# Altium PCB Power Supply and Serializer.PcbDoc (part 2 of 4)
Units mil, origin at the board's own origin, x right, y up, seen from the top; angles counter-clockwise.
Board outline 986 x 985 mil, 8 copper layers (TOP, GND1, INNER1, GND2, PWR1, INNER2, GND3, BOTTOM), stack 60.4 mil thick; 91 components, 64 nets, 288 pads, 200 vias.
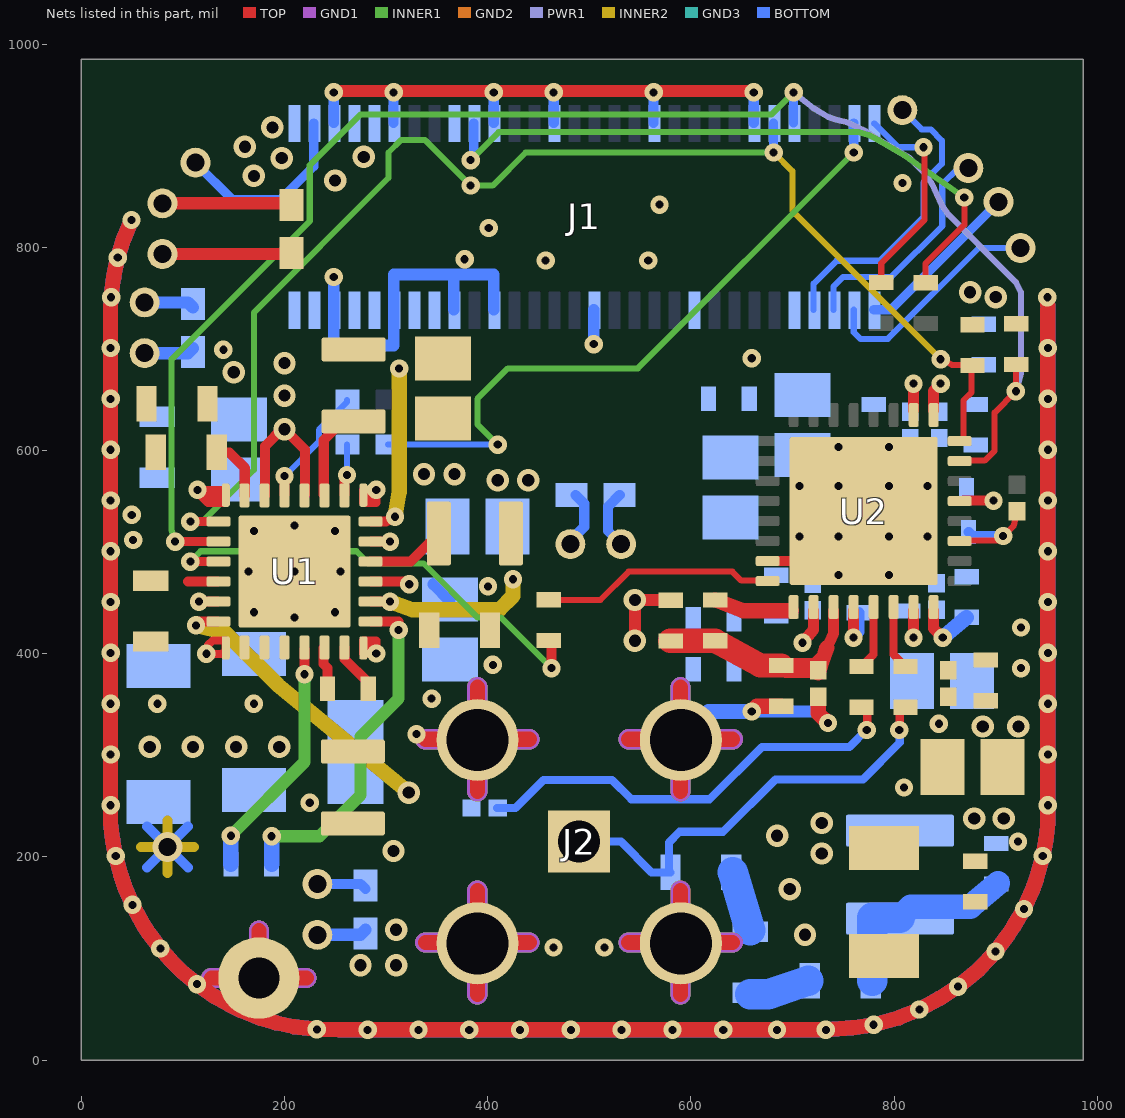
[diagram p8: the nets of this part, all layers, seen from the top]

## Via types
v1: diameter 18, hole 8, TOP to BOTTOM, 147 vias
v2: diameter 22, hole 12, TOP to BOTTOM, 36 vias
v3: diameter 19.68, hole 7.87, TOP to BOTTOM, 17 vias

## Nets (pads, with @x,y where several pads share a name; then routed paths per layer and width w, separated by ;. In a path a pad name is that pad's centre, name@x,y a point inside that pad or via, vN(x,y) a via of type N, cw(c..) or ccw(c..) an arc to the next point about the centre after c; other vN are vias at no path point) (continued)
DGND: C2.2 C3.2 C4.2 C5.2 C6.2 C7.2 C8.2 C9.2 C10.2 C11.2 C12.2 C13.2 C15.2 C16.2 C18.1 C19.2 C20.2 C21.2 C22.2 C24.2 C25.2 C26.2 C27.2 C28.2 C29.2 C30.2 C31.2 C32.2 C33.2 C34.2 C35.2 J1.5 J1.6 J1.11 J1.12 J1.18 J1.21 J1.22 J1.27 J1.32 J1.37 J1.42 J1.47 J1.52 J2.2 J2.3 J2.4 J2.5 R10.1 R14.1 R15.1 TP15.1 U1.5 U1.25 U1.A1 U1.A2 U1.A3 U1.A4 U2.7 U2.33@770,540.39 | length 11901.1
  TOP w8: v1@119.3,561.3 125.8,554.8 U1.A1@138.38,554.8 ; v1@119.3,561.3 138.38,561.3 U1.A1@138.38,554.8 ; v1@119.3,561.3 v1(114.3,561.3) 114.3,558.8 124.58,548.52 142.08,548.52 138.38,552.22 U1.A1@138.38,554.8 ; U1.A3@277.52,413.08 290.3,413.08 v1(290.3,400.3) ; U1.A3@277.52,413.08 277.52,400.3 v1(290.3,400.3) ; U1.A3@277.52,413.08 v1(290.3,400.3) ; U1.A4@277.52,548.52 277.52,561.3 v1(290.3,561.3) ; U1.A4@277.52,548.52 v1(290.3,561.3) ; U1.A4@277.52,548.52 290.3,548.52 v1(290.3,561.3) ; v1@124.8,399.8 138.52,399.8 142.08,403.36 142.08,413.08 129.3,413.08 124.8,408.58 v1@124.8,399.8
  TOP w9.8: v1(115.8,451.27) U1.5@133.89,451.27 ; U2.7@675.51,491.18 720.79,491.18 U2.33@770,540.39
  TOP w12: v1(248.4,952.5) 249.7,953.8 306.1,953.8 v1(307.4,952.5) 308.7,953.8 404.6,953.8 v1(405.9,952.5) 407.2,953.8 463.6,953.8 v1(464.9,952.5) 466.2,953.8 562,953.8 v1(563.3,952.5) 564.6,953.8 660.5,953.8 v1(661.8,952.5)
  TOP w15: v1(49.3,826.8) 41.3,807.3 v1(35.8,789.8) 31.8,770.3 v1(29.3,750.8) 28.8,738.3 v1(28.8,700.8) v1(28.8,650.8) v1(28.8,600.8) v1(28.8,550.8) v1(28.8,500.8) v1(28.8,450.8) v1(28.8,400.8) v1(28.8,350.8) v1(28.8,300.8) v1(28.8,250.8) 28.8,233.3 30.8,216.8 v1(33.8,200.8) 38.8,182.3 43.8,167.8 v1(50.3,152.8) 59.8,135.3 66.8,124.3 v1(77.8,109.8) 88.3,97.8 98.8,87.3 v1(113.8,74.8) 130.8,62.8 145.3,54.8 158.3,48.3 176.3,41.3 191.3,36.8 209.3,32.8 v1(231.8,30.3) 253.8,29.8 v1(281.8,29.8) v1(331.8,29.8) v1(381.8,29.8) v1(431.8,29.8) v1(481.8,29.8) v1(531.8,29.8) v1(581.8,29.8) v1(631.8,29.8) v1(684.8,29.8) v1(732.8,29.8) 758.8,31.8 v1(779.8,34.8) 804.8,41.8 v1(824.8,49.8) 844.8,60.8 v1(862.8,72.3) 883.8,89.8 v1(899.8,106.8) 911.8,122.8 917.8,131.8 v1(927.8,148.8) 935.8,166.8 939.8,177.8 v1(946.3,200.8) 949.3,216.8 951.3,233.3 v1(951.3,250.8) v1(951.3,300.8) v1(951.3,350.8) v1(951.3,400.8) v1(951.3,450.8) v1(951.3,500.8) v1(951.3,550.8) v1(951.3,600.8) v1(951.3,650.8) v1(951.3,700.8) 951.3,738.3 v1(950.8,750.8) ; 127.98,80.8 TP15.1@174.8,80.8 ; 174.8,127.62 TP15.1@174.8,80.8 ; 221.62,80.8 TP15.1@174.8,80.8 ; 338.61,115.8 J2.5@389.8,115.8 ; 338.61,315.8 J2.2@389.8,315.8 ; 389.8,64.61 J2.5@389.8,115.8 ; 389.8,166.99 J2.5@389.8,115.8 ; 389.8,264.61 J2.2@389.8,315.8 ; 389.8,366.99 J2.2@389.8,315.8 ; 440.99,115.8 J2.5@389.8,115.8 ; 440.99,315.8 J2.2@389.8,315.8 ; 538.61,115.8 J2.4@589.8,115.8 ; 538.61,315.8 J2.3@589.8,315.8 ; 589.8,64.61 J2.4@589.8,115.8 ; 589.8,166.99 J2.4@589.8,115.8 ; 589.8,264.61 J2.3@589.8,315.8 ; 589.8,366.99 J2.3@589.8,315.8 ; 640.99,115.8 J2.4@589.8,115.8 ; 640.99,315.8 J2.3@589.8,315.8 ; v1(659.8,343.22) 664.8,348.22 C21.2@688.8,348.22 ; C22.2@725.3,355.31 725.3,341.3 v1(734.8,331.8)
  GND1 w20: 127.98,80.8 TP15.1@174.8,80.8 ; 174.8,127.62 TP15.1@174.8,80.8 ; 221.62,80.8 TP15.1@174.8,80.8 ; 338.61,115.8 J2.5@389.8,115.8 ; 338.61,315.8 J2.2@389.8,315.8 ; 389.8,64.61 J2.5@389.8,115.8 ; 389.8,166.99 J2.5@389.8,115.8 ; 389.8,264.61 J2.2@389.8,315.8 ; 389.8,366.99 J2.2@389.8,315.8 ; 440.99,115.8 J2.5@389.8,115.8 ; 440.99,315.8 J2.2@389.8,315.8 ; 538.61,115.8 J2.4@589.8,115.8 ; 538.61,315.8 J2.3@589.8,315.8 ; 589.8,64.61 J2.4@589.8,115.8 ; 589.8,166.99 J2.4@589.8,115.8 ; 589.8,264.61 J2.3@589.8,315.8 ; 589.8,366.99 J2.3@589.8,315.8 ; 640.99,115.8 J2.4@589.8,115.8 ; 640.99,315.8 J2.3@589.8,315.8
  INNER1 w20: 127.98,80.8 TP15.1@174.8,80.8 ; 174.8,127.62 TP15.1@174.8,80.8 ; 221.62,80.8 TP15.1@174.8,80.8 ; 338.61,115.8 J2.5@389.8,115.8 ; 338.61,315.8 J2.2@389.8,315.8 ; 389.8,64.61 J2.5@389.8,115.8 ; 389.8,166.99 J2.5@389.8,115.8 ; 389.8,264.61 J2.2@389.8,315.8 ; 389.8,366.99 J2.2@389.8,315.8 ; 440.99,115.8 J2.5@389.8,115.8 ; 440.99,315.8 J2.2@389.8,315.8 ; 538.61,115.8 J2.4@589.8,115.8 ; 538.61,315.8 J2.3@589.8,315.8 ; 589.8,64.61 J2.4@589.8,115.8 ; 589.8,166.99 J2.4@589.8,115.8 ; 589.8,264.61 J2.3@589.8,315.8 ; 589.8,366.99 J2.3@589.8,315.8 ; 640.99,115.8 J2.4@589.8,115.8 ; 640.99,315.8 J2.3@589.8,315.8
  GND2 w20: 127.98,80.8 TP15.1@174.8,80.8 ; 174.8,127.62 TP15.1@174.8,80.8 ; 221.62,80.8 TP15.1@174.8,80.8 ; 338.61,115.8 J2.5@389.8,115.8 ; 338.61,315.8 J2.2@389.8,315.8 ; 389.8,64.61 J2.5@389.8,115.8 ; 389.8,166.99 J2.5@389.8,115.8 ; 389.8,264.61 J2.2@389.8,315.8 ; 389.8,366.99 J2.2@389.8,315.8 ; 440.99,115.8 J2.5@389.8,115.8 ; 440.99,315.8 J2.2@389.8,315.8 ; 538.61,115.8 J2.4@589.8,115.8 ; 538.61,315.8 J2.3@589.8,315.8 ; 589.8,64.61 J2.4@589.8,115.8 ; 589.8,166.99 J2.4@589.8,115.8 ; 589.8,264.61 J2.3@589.8,315.8 ; 589.8,366.99 J2.3@589.8,315.8 ; 640.99,115.8 J2.4@589.8,115.8 ; 640.99,315.8 J2.3@589.8,315.8
  GND3 w20: 127.98,80.8 TP15.1@174.8,80.8 ; 174.8,127.62 TP15.1@174.8,80.8 ; 221.62,80.8 TP15.1@174.8,80.8 ; 338.61,115.8 J2.5@389.8,115.8 ; 338.61,315.8 J2.2@389.8,315.8 ; 389.8,64.61 J2.5@389.8,115.8 ; 389.8,166.99 J2.5@389.8,115.8 ; 389.8,264.61 J2.2@389.8,315.8 ; 389.8,366.99 J2.2@389.8,315.8 ; 440.99,115.8 J2.5@389.8,115.8 ; 440.99,315.8 J2.2@389.8,315.8 ; 538.61,115.8 J2.4@589.8,115.8 ; 538.61,315.8 J2.3@589.8,315.8 ; 589.8,64.61 J2.4@589.8,115.8 ; 589.8,264.61 J2.3@589.8,315.8 ; 589.8,366.99 J2.3@589.8,315.8 ; 640.99,115.8 J2.4@589.8,115.8 ; 640.99,315.8 J2.3@589.8,315.8
  BOTTOM w10: J1.5@248.4,922.4 v1(248.4,952.5) ; J1.11@307.4,922.4 v1(307.4,952.5) ; J1.21@405.9,922.4 v1(405.9,952.5) ; J1.27@464.9,922.4 v1(464.9,952.5) ; J1.37@563.3,922.4 v1(563.3,952.5) ; J1.47@661.8,922.4 v1(661.8,952.5)
  BOTTOM w11.5: v1(248.4,770.8) 248.4,703.3 307.4,703.3 307.4,773.3 366.5,773.3 ; J1.18@366.5,738.5 366.5,773.3 ; J1.22@405.9,738.5 405.9,773.3 366.5,773.3 ; v1(504.3,704.7) J1.32@504.3,738.5
  BOTTOM w12: v1(248.4,952.5) 249.7,953.8 306.1,953.8 v1(307.4,952.5) 308.7,953.8 404.6,953.8 v1(405.9,952.5) 407.2,953.8 463.6,953.8 v1(464.9,952.5) 466.2,953.8 562,953.8 v1(563.3,952.5) 564.6,953.8 660.5,953.8 v1(661.8,952.5) ; v1(659.8,343.22) 723.38,343.22 v1(734.8,331.8)
  BOTTOM w15: v1(49.3,826.8) 41.3,807.3 v1(35.8,789.8) 31.8,770.3 v1(29.3,750.8) 28.8,738.3 v1(28.8,700.8) v1(28.8,650.8) v1(28.8,600.8) v1(28.8,550.8) v1(28.8,500.8) v1(28.8,450.8) v1(28.8,400.8) v1(28.8,350.8) v1(28.8,300.8) v1(28.8,250.8) 28.8,233.3 30.8,216.8 v1(33.8,200.8) 38.8,182.3 43.8,167.8 v1(50.3,152.8) 59.8,135.3 66.8,124.3 v1(77.8,109.8) 88.3,97.8 98.8,87.3 v1(113.8,74.8) 130.8,62.8 145.3,54.8 158.3,48.3 176.3,41.3 191.3,36.8 209.3,32.8 v1(231.8,30.3) 253.8,29.8 v1(281.8,29.8) v1(331.8,29.8) v1(381.8,29.8) v1(431.8,29.8) v1(481.8,29.8) v1(531.8,29.8) v1(581.8,29.8) v1(631.8,29.8) v1(684.8,29.8) v1(732.8,29.8) 758.8,31.8 v1(779.8,34.8) 804.8,41.8 v1(824.8,49.8) 844.8,60.8 v1(862.8,72.3) 883.8,89.8 v1(899.8,106.8) 911.8,122.8 917.8,131.8 v1(927.8,148.8) 935.8,166.8 939.8,177.8 v1(946.3,200.8) 949.3,216.8 951.3,233.3 v1(951.3,250.8) v1(951.3,300.8) v1(951.3,350.8) v1(951.3,400.8) v1(951.3,450.8) v1(951.3,500.8) v1(951.3,550.8) v1(951.3,600.8) v1(951.3,650.8) v1(951.3,700.8) 951.3,738.3 v1(950.8,750.8) ; 126.98,80.8 TP15.1@174.8,80.8 222.62,80.8 ; 337.61,315.8 J2.2@389.8,315.8 ; 389.8,63.61 J2.5@389.8,115.8 ; 389.8,167.99 J2.5@389.8,115.8 ; 389.8,367.99 J2.2@389.8,315.8 ; 441.99,115.8 J2.5@389.8,115.8 ; 441.99,315.8 J2.2@389.8,315.8 ; 537.61,115.8 589.8,115.8 589.8,63.61 ; 537.61,315.8 589.8,315.8 617.22,343.22 v1(659.8,343.22)
  BOTTOM w20: TP15.1@174.8,80.8 TP15.1@187.3,93.3
  other v1: 464.8,110.8 514.8,110.8 809.8,268.3 329.8,320.8 844,331 74.8,350.8 169.8,350.8 344.8,355.8 924.8,385.8 405,389 123,400 924.8,425.8 169.8,440.8 249.8,440.8 51,512 169.8,520.8 249.8,520.8 49.64,536.67 659.8,690.8 457,787 558,787 377.3,788.3 401,819 569,842 808.3,863.3
  other v2: 712.3,123.3 697.3,168.3 684.8,220.8 337.3,576.8 367.3,576.8
  other v3: 209.86,435.59 745.2,477.4 794.8,477.4 164.58,480.86 209.86,480.86 255.13,480.86 707.01,515.59 745.2,515.59 794.8,515.59 832.99,515.59 209.86,526.14 707.01,565.2 745.2,565.2 794.8,565.2 832.99,565.2 745.2,603.39 794.8,603.39
DOUTN: C17.1 U2.13 | length 59.9
  TOP w8: C17.1@767.83,387.4 779.64,399.21 U2.13@779.64,442.37
DOUTN_C: C17.2 R10.2 | length 435.8
  TOP w8: C17.2@767.83,347.24 773.48,341.59 v1@773.48,325.8
  BOTTOM w8: R10.2@409.29,248.3 427.3,248.3 454.8,275.8 522.3,275.8 541.3,256.8 618.31,256.8 669.81,308.3 755.98,308.3 v1@773.48,325.8
  other v1: 773,325
DOUTP: C14.1 U2.14 | length 59.9
  TOP w8: U2.14@799.33,442.37 799.33,399.21 C14.1@811.14,387.4
DOUTP_C: C14.2 J2.1 L6.1 | length 436.7
  TOP w8: v1@805.48,325.8 805.48,341.58 C14.2@811.14,347.24
  BOTTOM w8: J2.1@490,215 531,215 561.2,184.8 L6.1@578.3,184.8 ; L6.1@579.8,184.8 L6.1@578.3,184.8 ; v1@805.48,325.8 805.48,312.54 769.24,276.3 683.07,276.3 631.57,224.8 588.8,224.8 578.3,214.3 L6.1@578.3,184.8
  other v1: 805,325
I2C_SCL: J1.49 R11.1 U1.1 U2.24 | length 1304.3
  TOP w6: v1(845.8,689.8) 856.8,684.22 876.3,684.22 876.3,657.29 868.23,649.22 U2.24@868.23,609.7
  TOP w9: v1(107.3,530.01) U1.1@133.89,530.01
  INNER1 w6: v1(107.3,530.01) 119.01,530.01 169.8,580.8 169.8,735.8 302.3,868.3 302.3,893.3 314.8,905.8 338.2,905.8 v1(383.2,860.8) 404.8,860.8 437.3,893.3 v1(681.4,893.3)
  INNER2 w6: v1(681.4,893.3) 699.8,874.9 699.8,835.8 v1(845.8,689.8)
  BOTTOM w9: v1(681.4,893.3) J1.49@681.4,922.4
I2C_SDA: J1.51 R12.1 U1.2 U2.23 | length 1536.4
  TOP w6: U2.23@868.23,590.01 889.01,590.01 898.8,599.8 898.8,637.3 v1(919.8,658.3) R12.1@919.8,684.22
  TOP w9: v1(92.3,510.33) U1.2@133.89,510.33
  INNER1 w6: v1(92.3,510.33) 88.8,521.8 88.8,689.8 224.8,825.8 224.8,880.8 274.8,930.8 679.4,930.8 v1(701.1,952.5)
  PWR1 w6: v1(701.1,952.5) 719.95,937.3 735.18,928.28 742.3,925.8 754.66,922.71 771.54,914.64 784.8,905.8 814.8,888.3 829.8,873.3 836.87,863.01 846.93,841.33 853.55,832.05 919.8,765.8 924.8,755.8 924.8,675.8 v1(919.8,658.3)
  BOTTOM w9: J1.51@701.1,922.4 v1(701.1,952.5)
IMG_GP2: J1.57 R6.1 | length 661.4
  INNER1 w6: v1(409.8,605.8) 389.8,625.8 389.8,650.8 419.8,680.8 547.7,680.8 v1(760.2,893.3)
  BOTTOM w6: R6.1@301.68,605.8 v1(409.8,605.8)
  BOTTOM w9: v1(760.2,893.3) J1.57@760.2,922.4
IMG_GP3: J1.59 R8.2 | length 209.3
  TOP w6: R8.2@787.3,765.38 787.3,784.3 829.8,826.8 829.8,897.61 v1(828.98,898.44)
  BOTTOM w6: J1.59@780.43,921.93 803.93,898.44 v1(828.98,898.44)
IMG_GP4: J1.54 TP4.1 | length 295.1
  BOTTOM w6: J1.54@720.8,738.5 720.8,764.3 743.3,786.8 785.8,786.8 828.8,829.8 828.8,863.81 847.04,882.05 847.04,904.96 836,916 827,916 TP4.1@808,935
IMG_GP5: J1.56 TP6.1 | length 228.1
  BOTTOM w6: J1.56@740.5,738.5 740.5,761.5 749.8,770.8 797.3,770.8 847.3,820.8 847.3,862.3 863,878 TP6.1@873,878
IMG_GP6: J1.58 TP7.1 | length 226
  BOTTOM w6: J1.58@760.2,738.5 760.2,716.4 766.8,709.8 793.8,709.8 883.3,799.3 TP7.1@924.3,799.3
IMG_HSYNC: J1.17
IMG_VSYNC: J1.19 R17.2 | length 653.4
  TOP w6: R17.2@830.8,765.38 830.8,783.8 869.05,822.05 v1(869.05,849.05)
  INNER1 w6: v1(383.2,885.8) 410.7,913.3 764.8,913.3 774.73,910.69 784.59,905.47 809.55,890.83 v1(869.05,849.05)
  BOTTOM w9: v1(383.2,885.8) 386.2,888.8 J1.19@386.2,922.4
LPF1: C23.2 U2.9 | length 79
  TOP w8: U2.9@698.8,442.37 U2.9@700.9,442.37
  TOP w15: C23.2@623.8,452.87 651.5,442.37 U2.9@698.8,442.37
LPF2: C35.1 U2.12 | length 53.3
  TOP w11: v1(759.96,415.8) U2.12@759.96,442.37
  BOTTOM w11: v1(759.96,415.8) 759.96,416.32 765.22,421.58 C35.1@765.22,440.38
NetC1_1: C1.1 L1.1 U1.11 | length 39.4
  TOP w10: U1.11@238.35,405.43 238.35,389.89 242.23,386.01 C1.1@242.23,367.66
NetC1_2: C1.2 U1.12 | length 50.1
  TOP w9.8: U1.12@259.07,406.06 259.07,394.74 282.3,371.51 C1.2@282.3,365.59
NetC4_1: C4.1 L1.2 R1.1 TP1.1 U1.6 | length 341.8
  TOP w9.8: v1(112.8,427.9) 116.49,431.59 U1.6@133.89,431.59
  INNER2 w15: v1(112.8,427.9) 141.66,420.94 193.6,369 v2(322.3,263.3)
  BOTTOM w10: TP1.1@232.3,173.3 274.88,173.3 R1.1@279.8,168.38
  other v1: 224.8,253.3
  other v2: 307.3,205.8
NetC5_1: C5.1 L2.2 R2.1 TP3.1 U1.18 | length 297.7
  TOP w9.8: U1.18@285.71,530.01 300.01,530.01 v1(308.8,534.8)
  TOP w12: TP3.1@79.8,793.3 199.88,793.3 R2.1@204.8,798.22
  INNER2 w15: v1(308.8,534.8) 312.8,558.92 v1(312.8,680.8)
NetC9_1: C9.1 L3.2 R3.1 TP9.1 U1.14 | length 220.4
  TOP w9.8: U1.14@285.71,451.27 v1(303.8,451.27)
  INNER2 w15: v1(303.8,451.27) 325.92,443.3 411.3,443.3 424.8,456.8 v1(424.8,473.3)
  BOTTOM w10: TP9.1@481.3,507.8 481.3,511.3 495,525 495,547.52 R3.1@486.22,556.3
  other v2: 409.8,570.8 439.8,570.8
NetC10_1: C10.1 U1.4 | length 29.1
  TOP w9.8: 104.8,470.96 U1.4@133.89,470.96
NetC11_1: C11.1 C12.1 R4.2 TP11.1 U1.24 | length 110.6
  TOP w10: C11.1@133.12,598.09 145.62,598.09 160.85,582.87 U1.24@160.85,555.88
  BOTTOM w12: TP11.1@62.3,695.8 104.88,695.8 R4.2@109.8,700.72
  other v1: 139.77,699.11
  other v2: 150,677
NetC19_1: C19.1 C20.1 L10.2 U2.25 | length 29.5
  TOP w11: U2.25@838.7,639.23 838.7,658.7 v1(845.8,665.8)
NetC21_1: C21.1 C22.1 C23.1 L9.2 U2.11 | length 263.5
  TOP w11: 733.8,405.8 740.27,419.8 U2.11@740.27,442.37
  TOP w15: 733.8,405.8 730.49,396.25 ; 730.49,396.25 722.62,388.38 688.8,388.38 693.38,383.8 722.79,383.8 725.3,381.29 730.49,396.25
  TOP w24: L9.2@579.8,412.71 623.8,412.71 668.31,388.38 C21.1@688.8,388.38
NetC24_1: C24.1 C25.1 L4.2 U2.16 | length 61.1
  TOP w11: U2.16@838.7,442.37 838.7,424.9 v1(847.8,415.8)
  BOTTOM w15: v1(847.8,415.8) C24.1@871.3,435.72
NetC26_1: C26.1 C27.1 C28.1 L11.2 U2.26 | length 26.6
  TOP w11: U2.26@819.01,639.23 v1(819.01,665.8)
NetC29_1: C29.1 C30.1 C31.1 L12.2 U2.15 | length 26.6
  TOP w11: v1(819.01,415.8) U2.15@819.01,442.37
NetC32_1: C32.1 C33.1 C34.1 L13.2 U2.10 | length 35.5
  TOP w11: v1(709.8,410.8) 720.59,423.59 U2.10@720.59,442.37
NetL2_1: L2.1 U1.20 | length 89.4
  TOP w10: U1.20@238.51,556.94 238.51,610.35 253.52,625.37 L2.1@268.3,625.37
NetL3_1: L3.1 U1.16 | length 78.6
  TOP w9.8: U1.16@284.66,490.7 324.27,490.7 L3.1@351.87,518.3
NetL5_1: L5.1 L8.2 R9.1 | length 198.9
  BOTTOM w24: L5.1@805.7,140.18 816.32,150.8 874.8,150.8 R9.1@902.2,174.12
  BOTTOM w30: L8.2@778.4,78.1 778.4,140.18 L5.1@805.7,140.18
NetL6_2: L6.2 L7.1 | length 59.6
  BOTTOM w30: L6.2@641.3,184.8 L7.1@658.3,127.7
NetL7_2: L7.2 L8.1 | length 59.3
  BOTTOM w30: L7.2@658.3,64.7 675.61,64.7 L8.1@715.4,78.1
NetR5_2: R5.2 U1.22 | length 118.6
  TOP w9.8: U1.22@199.96,556.71 v1(199.96,574.8)
  BOTTOM w6: v1(199.96,574.8) 233.8,608.64 233.8,620.3 261.52,648.02 R5.2@261.52,649.8
NetR6_2: R6.2 U1.19 | length 50.1
  TOP w9.8: U1.19@259.01,556.71 259.01,573.3 v1(261.51,575.8)
  BOTTOM w6: v1(261.51,575.8) R6.2@261.51,605.79
NetR7_2: R7.2 U1.10 | length 243.1
  TOP w10: v1@218.66,380.78 v1(219.64,379.8) U1.10@219.64,404.45
  INNER1 w12: v1(147.14,220.8) 219.64,293.3 v1(219.64,379.8)
  BOTTOM w15: R7.2@147.14,192.8 v1(147.14,220.8)
NetR13_2: R13.2 R15.2 U2.19 | length 105.8
  TOP w6: U2.19@868.23,511.27 902.77,511.27 v1(907.3,515.8) 918.15,526.65 R13.2@920.8,540.31
  BOTTOM w10: R15.2@873.38,519.8 877.38,515.8 v1(907.3,515.8)
NetR14_2: R14.2 U2.21 | length 25.6
  TOP w10: U2.21@868.23,550.64 v1@893.8,550.64
  other v1: 897.85,550.66
NetR16_2: R16.2 U2.8 | length 223.8
  TOP w6: R16.2@462.8,452.87 486.3,452.87 509.8,452.87 510.88,452.87 538.81,480.8 640.79,480.8 649.69,471.9 U2.8@671.37,471.9
PMIC_RSTOUT: R16.1 U1.3 | length 460.8
  TOP w9: v1(107.3,490.64) U1.3@133.89,490.64
  TOP w10: v1(462.8,385.8) R16.1@462.8,412.71
  INNER1 w6: v1(107.3,490.64) 117.46,500.8 270.8,500.8 282.8,488.8 336.8,488.8 389.8,435.8 412.8,435.8 v1(462.8,385.8)
SPARE: J1.60 TP8.1 | length 166.9
  BOTTOM w9: J1.60@779.9,738.5 796.5,738.5 TP8.1@902.8,844.8
VDD_1V8: C18.2 J1.7 J1.9 L4.1 L9.1 L10.1 R2.2 R11.2 R12.2 TP5.1 U1.17 | length 220.6
  TOP w9.8: U1.17@285.71,510.33 v1(303.8,510.33)
  TOP w12: TP5.1@79.8,843.3 205.18,843.3 R2.2@207.06,841.42 ; v2(544.8,412.71) v2(544.8,452.87) L9.1@579.14,452.87
  other v2: 887.3,328.3 922.3,328.3 900,751 874.8,755.8 249.8,865.8 278,889
VDD_3V5: C6.1 C7.1 C8.1 J1.2 J1.4 R1.2 TP2.1 U1.15 U1.21 U1.23 | length 258.3
  TOP w9.8: U1.15@285.71,470.96 320.14,470.96 v1(322.8,468.3)
  TOP w10: U1.23@180.71,555.62 180.71,604.21 198.75,622.25 v2(200,621) 219.98,601.02 U1.21@219.98,556.45
  BOTTOM w12: TP2.1@232.3,123.3 274.88,123.3 R1.2@279.8,128.22 ; C6.1@346.83,468.3 C6.1@362.3,452.83
  other v1: 400.3,466.3
  other v2: 274.8,93.3 309.8,93.3 309.8,128.3 200,654 200,686
VDD_AVDD: J1.8 J1.10 R4.1 TP12.1 | length 49.5
  BOTTOM w12: TP12.1@62.3,745.8 104.88,745.8 R4.1@109.8,740.88
VDD_DVDD: J1.14 J1.16 L11.1 L12.1 L13.1 R3.2 TP10.1 | length 58.6
  BOTTOM w10: R3.2@529.92,556.3 518.39,544.77 518.39,520.71 TP10.1@531.3,507.8
VDD_SPARE: J1.3 TP13.1 | length 187.8
  BOTTOM w9: TP13.1@112.3,883.3 148.8,846.8 195.8,846.8 228.7,879.7 J1.3@228.7,922.4
VDD_VIN: C2.1 C3.1 C15.1 C16.1 J1.1 L5.2 R9.2 TP14.1 U1.7 U1.8 U1.9 | length 217.7
  INNER2 w10: 59,209.8 TP14.1@84.8,209.8 ; 84.8,184 TP14.1@84.8,209.8 ; 84.8,235.6 TP14.1@84.8,209.8 ; 110.6,209.8 TP14.1@84.8,209.8
  BOTTOM w10: 64.56,189.56 TP14.1@84.8,209.8 ; 64.56,230.04 TP14.1@84.8,209.8 ; 105.04,189.56 TP14.1@84.8,209.8 ; 105.04,230.04 TP14.1@84.8,209.8
  other v1: 922,215
  other v2: 728.8,203.3 728.8,233.3 878.8,237.8 907.8,237.8 67.3,308.3 109.8,308.3 152.3,308.3 194.8,308.3 169.8,870.3 197.3,887.8 161,899 188,918
VREG: C13.1 R7.1 U1.13 | length 344.7
  TOP w9.8: U1.13@285.71,431.59 312.3,431.59 v1(312.3,423.3)
  INNER1 w12: v1(187.3,220.3) 234.3,220.3 274.8,260.8 274.8,318.3 312.3,355.8 v1(312.3,423.3)
  BOTTOM w15: R7.1@187.3,192.8 v1(187.3,220.3)
pads on no net: FID1.1 FID2.1 FID3.1 J1.15 J1.20 J1.24 J1.26 J1.28 J1.30 J1.34 J1.36 J1.38 J1.40 J1.44 J1.46 J1.48 J1.50 U1. U2.20 U2.22 U2.33@720.39,490.79 U2.33@720.39,540.39 U2.33@720.39,590 U2.33@770,490.79 U2.33@770,540.39 U2.33@770,590 U2.33@819.61,490.79 U2.33@819.61,540.39 U2.33@819.61,590
copper on no net:
  other v1: 844.8,95.8 872.3,113.3 464.8,320.8 514.8,320.8

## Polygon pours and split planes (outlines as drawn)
no net on M16 Courtyards Bottom (solid): 52 vertices, not listed, extent 82.44,461.28 94.11,491.23
no net on M16 Courtyards Bottom (solid): 52 vertices, not listed, extent 218.11,461.26 229.61,491.24
no net on M16 Courtyards Bottom (solid): 164 vertices, not listed, extent 234.62,446.26 261.13,491.53
no net on M16 Courtyards Bottom (solid): 130 vertices, not listed, extent 47.28,461.26 77.63,491.74
no net on M16 Courtyards Bottom (solid): 112 vertices, not listed, extent 97.53,461.34 118.46,491.71
no net on M16 Courtyards Bottom (solid): 140 vertices, not listed, extent 121.64,460.67 147.44,491.74
no net on M16 Courtyards Bottom (solid): 148 vertices, not listed, extent 151.99,460.66 177.83,491.72
no net on M16 Courtyards Bottom (solid): 136 vertices, not listed, extent 183.03,461.26 213.19,491.74
no net on M16 Courtyards Bottom (solid): 144 vertices, not listed, extent 266.31,461.26 296.61,491.73
no net on M16 Courtyards Bottom (solid): 54 vertices, not listed, extent 300.11,461.34 321.61,501.76
no net on M16 Courtyards Bottom (solid): 42 vertices, not listed, extent 81.64,496.43 89.79,504.4
no net on M16 Courtyards Bottom (solid): 50 vertices, not listed, extent 217.19,496.44 225.44,504.43
no net on M16 Courtyards Bottom (solid): 842 vertices, not listed, extent 195.48,510.25 231.27,563.59
no net on M16 Courtyards Bottom (solid): 102 vertices, not listed, extent 227.1,510.61 270.61,563.57
no net on M16 Courtyards Bottom (solid): 52 vertices, not listed, extent 44.44,475.28 56.11,505.23
no net on M16 Courtyards Bottom (solid): 52 vertices, not listed, extent 180.11,475.26 191.61,505.24
no net on M16 Courtyards Bottom (solid): 164 vertices, not listed, extent 196.62,460.26 223.13,505.53
no net on M16 Courtyards Bottom (solid): 130 vertices, not listed, extent 9.28,475.26 39.63,505.74
no net on M16 Courtyards Bottom (solid): 112 vertices, not listed, extent 59.53,475.34 80.46,505.71
no net on M16 Courtyards Bottom (solid): 140 vertices, not listed, extent 83.64,474.67 109.44,505.74
no net on M16 Courtyards Bottom (solid): 148 vertices, not listed, extent 113.99,474.66 139.83,505.72
no net on M16 Courtyards Bottom (solid): 136 vertices, not listed, extent 145.03,475.26 175.19,505.74
no net on M16 Courtyards Bottom (solid): 144 vertices, not listed, extent 228.31,475.26 258.61,505.73
no net on M16 Courtyards Bottom (solid): 54 vertices, not listed, extent 262.11,475.34 283.61,515.76
no net on M16 Courtyards Bottom (solid): 42 vertices, not listed, extent 43.64,510.43 51.79,518.4
no net on M16 Courtyards Bottom (solid): 50 vertices, not listed, extent 179.19,510.44 187.44,518.43
no net on M16 Courtyards Bottom (solid): 842 vertices, not listed, extent 157.48,524.25 193.27,577.59
no net on M16 Courtyards Bottom (solid): 102 vertices, not listed, extent 189.1,524.61 232.61,577.57
DGND on TOP "TOP-DGND 3" (solid, pour order 216): 136 vertices, not listed, extent 22.3,501.3 136.72,668.3
DGND on TOP "TOP-DGND 2" (solid, pour order 214): 59 vertices, not listed, extent 22.3,288.3 142.78,430.8
DGND on TOP "TOP-DGND 6" (solid, pour order 212): 210 vertices, not listed, extent 22.3,58.39 225.59,288.3
NetL3_1 on TOP "TOP-N16889099" (solid, pour order 144): 94 vertices, not listed, extent 274.3,481.8 373.8,549.8
NetC11_1 on TOP "TOP-N16894539" (solid, pour order 142): 50 vertices, not listed, extent 99.8,545.3 165.3,705.8
NetC9_1 on TOP "TOP-N16889103" (solid, pour order 140): 64 vertices, not listed, extent 397.3,463.3 454.8,583.3
NetC5_1 on TOP "TOP-N16889018" (solid, pour order 138): 139 vertices, not listed, extent 187.3,670.8 379.8,810.8
NetL2_1 on TOP "TOP-N16889014" (solid, pour order 136): 45 vertices, not listed, extent 233.3,545.3 301.3,646.3
NetC4_1 on TOP "TOP-N16887352" (solid, pour order 134): 315.8,274.8 326.8,274.8 333.8,267.8 333.8,214.8 312.3,193.3 247.3,193.3 214.8,225.8 214.8,265.8 306.8,265.8 315.8,274.8
NetC1_1 on TOP "TOP-N16887349" (solid, pour order 132): 29 vertices, not listed, extent 231.8,288.8 289.8,416.3
NetC10_1 on TOP "TOP-V1P8_INT" (solid, pour order 130): 47 vertices, not listed, extent 49.8,455.8 114.8,490.8
VREG on TOP "TOP-VREG" (solid, pour order 128): 30 vertices, not listed, extent 287.3,400.8 359.8,445.8
NetC24_1 on TOP "TOP-VDD_DRV" (solid, pour order 126): 839.8,410.8 833.8,422.8 833.8,454.8 835.8,456.8 842.3,456.8 873.3,425.8 887.3,425.8 907.3,405.8 907.3,375.8 839.8,375.8 839.8,410.8
VDD_VIN on TOP "TOP-VDD_VIN 2" (solid, pour order 124): 76 vertices, not listed, extent 137.3,288.3 212.3,416.3
VDD_VIN on TOP "TOP-VDD_VIN 1" (solid, pour order 122): 23 vertices, not listed, extent 714.8,183.3 934.8,248.8
VDD_VIN on TOP "TOP-VDD_VIN" (solid, pour order 120): 59 vertices, not listed, extent 52.3,288.3 184.8,416.3
DGND on TOP "TOP-DGND 7" (solid, pour order 118): 27 vertices, not listed, extent 274.8,545.8 382.3,650.8
DGND on TOP "TOP-DGND 5" (solid, pour order 116): 712 vertices, not listed, extent 186.81,23.3 943.03,450.8
DGND on TOP "TOP-DGND 4" (solid, pour order 114): 291 vertices, not listed, extent 904.8,375.8 957.3,660.8
VDD_3V5 on TOP "TOP-VDD_3V5" (solid, pour order 112): 71 vertices, not listed, extent 172.32,545.3 226.28,705.8
VDD_1V8 on TOP "TOP-VDD_1V8 2" (solid, pour order 110): 859.8,768.3 904.8,768.3 934.8,738.3 934.8,710.8 859.8,710.8 859.8,768.3
VDD_1V8 on TOP "TOP-VDD_1V8" (solid, pour order 108): 352 vertices, not listed, extent 187.3,825.8 432.3,940.78
VDD_1V8 on TOP "TOP-VDD_1V8 1" (solid, pour order 106): 882.3,315.8 874.8,323.3 874.8,365.8 934.8,365.8 934.8,258.3 882.3,258.3 882.3,315.8
NetC4_1 on BOTTOM "BOTTOM-N16887352" (solid, pour order 186): 304.8,295.8 327.3,273.3 327.3,155.8 259.8,155.8 259.8,193.3 214.8,238.3 214.8,268.3 242.3,295.8 304.8,295.8
DGND on BOTTOM "BOTTOM-DGND 1" (solid, pour order 158): 623 vertices, not listed, extent 612.3,260.8 957.3,763.3
NetC11_1 on BOTTOM "BOTTOM-N16894539" (solid, pour order 190): 144.8,670.8 92.3,670.8 92.3,713.3 152.3,713.3 152.3,678.3 144.8,670.8
NetC9_1 on BOTTOM "BOTTOM-N16889103" (solid, pour order 188): 487.3,583.3 499.8,570.8 499.8,535.8 469.8,535.8 454.8,520.8 454.8,495.8 392.3,495.8 392.3,583.3 487.3,583.3
VDD_AVDD on BOTTOM "BOTTOM-VDD_AVDD" (solid, pour order 184): 73 vertices, not listed, extent 92.3,720.2 293.6,825.8
VDD_DVDD on BOTTOM "BOTTOM-VDD_DVDD" (solid, pour order 182): 184 vertices, not listed, extent 321.2,365.8 632.3,756.8
NetC26_1 on BOTTOM "BOTTOM-VDDD_CAP" (solid, pour order 180): 47 vertices, not listed, extent 644.8,629.8 827.8,680.8
NetC29_1 on BOTTOM "BOTTOM-VDDDRV_CAP" (solid, pour order 178): 79 vertices, not listed, extent 627.3,345.8 842.8,450.3
NetC32_1 on BOTTOM "BOTTOM-VDDPLL_CAP" (solid, pour order 176): 19 vertices, not listed, extent 612.3,400.8 727.3,553.3
NetC19_1 on BOTTOM "BOTTOM-VDDD" (solid, pour order 174): 101 vertices, not listed, extent 837.3,629.8 910.41,695.8
NetR14_2 on BOTTOM "BOTTOM-MODE" (solid, pour order 172): 883.57,576.4 903.76,556.21 903.76,549.98 896.09,542.31 873.29,542.31 861.8,553.8 861.8,572 866.2,576.4
VDD_VIN on BOTTOM "BOTTOM-VDD_VIN 2" (solid, pour order 170): 57 vertices, not listed, extent 122.42,858.32 214.8,944.8
VDD_VIN on BOTTOM "BOTTOM-VDD_VIN 1" (solid, pour order 168): 932.3,255.8 932.3,213.3 924.8,200.8 879.8,200.8 869.8,190.8 722.3,190.8 717.3,195.8 717.3,243.3 722.3,248.3 842.3,248.3 849.8,255.8 932.3,255.8
VDD_VIN on BOTTOM "BOTTOM-VDD_VIN" (solid, pour order 166): 204.8,323.3 214.8,313.3 214.8,285.8 204.8,275.8 204.8,238.3 134.8,238.3 124.8,228.3 124.8,178.3 67.3,178.3 59.8,185.8 49.8,205.8 47.3,215.8 44.8,240.8 44.8,323.3 204.8,323.3
DGND on BOTTOM "BOTTOM-DGND 4" (solid, pour order 164): 1087 vertices, not listed, extent 22.3,23.3 624.8,594.78
DGND on BOTTOM "BOTTOM-DGND 3" (solid, pour order 162): 111 vertices, not listed, extent 40.96,60.57 140.92,165.8
DGND on BOTTOM "BOTTOM-DGND 2" (solid, pour order 160): 327 vertices, not listed, extent 301.6,767.8 468.35,957.5
DGND on BOTTOM "BOTTOM-DGND" (solid, pour order 156): 148 vertices, not listed, extent 494.8,680.8 709.8,755.8
VDD_3V5 on BOTTOM "BOTTOM-VDD_3V5 2" (solid, pour order 154): 344.8,435.8 319.8,460.8 319.8,468.4 332.2,480.8 397.3,480.8 407.8,470.3 408.3,467.3 408.3,465.3 407.8,461.8 407.3,460.8 382.3,435.8
VDD_3V5 on BOTTOM "BOTTOM-VDD_3V5 1" (solid, pour order 152): 149.8,660.8 164.8,675.8 164.8,743.3 178.3,756.8 234.6,756.8 234.6,643.1 221.8,630.3 221.8,615.3 212.3,605.8 189.8,605.8 184.8,610.8 47.3,610.8 47.3,660.8 149.8,660.8
VDD_3V5 on BOTTOM "BOTTOM-VDD_3V5" (solid, pour order 150): 259.8,78.3 259.8,140.8 327.3,140.8 327.3,78.3 259.8,78.3
VDD_1V8 on BOTTOM "BOTTOM-VDD_1V8 1" (solid, pour order 148): 261.8,940.78 293.8,940.78 293.8,845.8 237.3,845.8 237.3,870.8 261.8,895.3 261.8,940.78
VDD_1V8 on BOTTOM "BOTTOM-VDD_1V8" (solid, pour order 146): 870.3,768.3 914.8,768.3 914.8,715.8 909.8,710.8 854.8,710.8 854.8,752.8 870.3,768.3
VDD_VIN on INNER2 "INNER2-VDD_VIN" (solid, pour order 192): 2208 vertices, not listed, extent 43.51,44.51 936.49,937.49
DGND on INNER1 "INNER1-DGND 3" (solid, pour order 200): 654 vertices, not listed, extent 70.89,705.14 687.76,961.4
DGND on INNER1 "INNER1-DGND 2" (solid, pour order 198): 2870 vertices, not listed, extent 19.6,20.6 960.4,902.28
DGND on INNER1 "INNER1-DGND 1" (solid, pour order 196): 527 vertices, not listed, extent 106.22,499.82 328.78,874.67
DGND on INNER1 "INNER1-DGND" (solid, pour order 194): 156 vertices, not listed, extent 99.82,541.72 158.78,672.52
DGND on GND3 "GND3-DGND" (solid, pour order 202): 1556 vertices, not listed, extent 19.6,20.6 960.4,961.4
DGND on GND1 "GND1-DGND" (solid, pour order 204): 1556 vertices, not listed, extent 19.6,20.6 960.4,961.4
DGND on GND2 "GND2-DGND" (solid, pour order 206): 1556 vertices, not listed, extent 19.6,20.6 960.4,961.4
VDD_3V5 on PWR1 "PWR1-VDD_3V5" (solid, pour order 210): 1112 vertices, not listed, extent 44.8,45.8 434.8,760.8
VDD_1V8 on PWR1 "PWR1-VDD_1V8" (solid, pour order 208): 2399 vertices, not listed, extent 88.16,44.51 936.49,937.49

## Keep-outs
GND1:
  region: 753,396.3 753,338.3 757,334.3 769.8,334.3 771.3,334.8 775.8,334.8 777.3,334.3 801.8,334.3 803.3,334.8 807.3,334.8 808.8,334.3 822,334.3 826,338.3 826,396.3 822,400.3 757,400.3 753,396.3
INNER1:
  region: 752.5,396.8 752.5,337.8 756.5,333.8 768.3,333.8 771.3,334.8 775.8,334.8 778.8,333.8 800.3,333.8 803.3,334.8 807.3,334.8 810.3,333.8 822.5,333.8 826.5,337.8 826.5,396.8 822.5,400.8 756.5,400.8 752.5,396.8
GND2:
  region: 752,397.3 752,337.3 756,333.3 766.8,333.3 771.3,334.8 775.8,334.8 780.3,333.3 798.8,333.3 803.3,334.8 807.3,334.8 811.8,333.3 823,333.3 827,337.3 827,397.3 823,401.3 756,401.3 752,397.3
PWR1:
  region: 558.8,200.8 558.8,168.8 563.8,163.8 592.3,163.8 597.3,168.8 597.3,200.8 592.3,205.8 563.8,205.8 558.8,200.8
  region: 827.5,397.8 827.5,336.8 823.5,332.8 813.3,332.8 807.3,334.8 803.3,334.8 797.3,332.8 781.8,332.8 775.8,334.8 771.3,334.8 765.3,332.8 755.5,332.8 751.5,336.8 751.5,397.8 755.5,401.8 823.5,401.8 827.5,397.8
INNER2:
  region: 559.3,200.3 559.3,169.3 564.3,164.3 591.8,164.3 596.8,169.3 596.8,200.3 591.8,205.3 564.3,205.3 559.3,200.3
  region: 751,336.3 755,332.3 763.8,332.3 771.3,334.8 775.8,334.8 783.3,332.3 795.8,332.3 803.3,334.8 807.3,334.8 814.8,332.3 824,332.3 828,336.3 828,398.3 824,402.3 755,402.3 751,398.3 751,336.3
GND3:
  region: 559.8,199.8 559.8,169.8 564.8,164.8 591.3,164.8 596.3,169.8 596.3,199.8 591.3,204.8 564.8,204.8 559.8,199.8
Keep-Out Layer:
  text ".Layer_Name" at 577,-858.49 h60

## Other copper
TOP:
  drawing of 71 lines, arcs and shapes, not listed
  text ".Layer_Name" at 577,-858.49 h60
GND1:
  pour cut-out: 323.63,205.8 322.39,212.05 318.85,217.35 313.55,220.89 307.3,222.13 301.05,220.89 295.75,217.35 292.21,212.05 290.97,205.8 292.21,199.55 295.75,194.25 301.05,190.71 307.3,189.47 313.55,190.71 318.85,194.25 322.39,199.55 323.63,205.8
  pour cut-out: 912.03,550.94 910.94,556.41 907.84,561.05 903.21,564.15 897.74,565.24 892.26,564.15 887.63,561.05 884.53,556.41 883.44,550.94 884.53,545.47 887.63,540.83 892.26,537.73 897.74,536.65 903.21,537.73 907.84,540.83 910.94,545.47 912.03,550.94
  pour cut-out: 935.09,590.8 934.01,596.27 930.91,600.91 926.27,604.01 920.8,605.09 915.33,604.01 910.69,600.91 907.59,596.27 906.51,590.8 907.59,585.33 910.69,580.69 915.33,577.59 920.8,576.51 926.27,577.59 930.91,580.69 934.01,585.33 935.09,590.8
  pour cut-out: 774.49,893.3 773.41,898.77 770.31,903.41 765.67,906.51 760.2,907.59 754.73,906.51 750.09,903.41 746.99,898.77 745.91,893.3 746.99,887.83 750.09,883.19 754.73,880.09 760.2,879.01 765.67,880.09 770.31,883.19 773.41,887.83 774.49,893.3
  pour cut-out: 735.09,893.3 734.01,898.77 730.91,903.41 726.27,906.51 720.8,907.59 715.33,906.51 710.69,903.41 707.59,898.77 706.51,893.3 707.59,887.83 710.69,883.19 715.33,880.09 720.8,879.01 726.27,880.09 730.91,883.19 734.01,887.83 735.09,893.3
  pour cut-out: 724.09,410.8 723.01,416.27 719.91,420.91 715.27,424.01 709.8,425.09 704.33,424.01 699.69,420.91 696.59,416.27 695.51,410.8 696.59,405.33 699.69,400.69 704.33,397.59 709.8,396.51 715.27,397.59 719.91,400.69 723.01,405.33 724.09,410.8
  pour cut-out: 695.69,893.3 694.61,898.77 691.51,903.41 686.87,906.51 681.4,907.59 675.93,906.51 671.29,903.41 668.19,898.77 667.11,893.3 668.19,887.83 671.29,883.19 675.93,880.09 681.4,879.01 686.87,880.09 691.51,883.19 694.61,887.83 695.69,893.3
  pour cut-out: 561.13,452.87 559.89,459.12 556.35,464.42 551.05,467.96 544.8,469.2 538.55,467.96 533.25,464.42 529.71,459.12 528.47,452.87 529.71,446.62 533.25,441.32 538.55,437.78 544.8,436.54 551.05,437.78 556.35,441.32 559.89,446.62 561.13,452.87
  pour cut-out: 561.13,412.71 559.89,418.96 556.35,424.26 551.05,427.8 544.8,429.04 538.55,427.8 533.25,424.26 529.71,418.96 528.47,412.71 529.71,406.46 533.25,401.16 538.55,397.62 544.8,396.38 551.05,397.62 556.35,401.16 559.89,406.46 561.13,412.71
  pour cut-out: 639.41,315.8 637.72,328.64 632.77,340.61 624.88,350.88 614.61,358.77 602.64,363.72 589.8,365.41 576.96,363.72 564.99,358.77 554.72,350.88 546.83,340.61 541.88,328.64 540.19,315.8 541.88,302.96 546.83,290.99 554.72,280.72 564.99,272.83 576.96,267.88 589.8,266.19 602.64,267.88 614.61,272.83 624.88,280.72 632.77,290.99 637.72,302.96 639.41,315.8
  pour cut-out: 639.41,115.8 637.72,128.64 632.77,140.61 624.88,150.88 614.61,158.77 602.64,163.72 589.8,165.41 576.96,163.72 564.99,158.77 554.72,150.88 546.83,140.61 541.88,128.64 540.19,115.8 541.88,102.96 546.83,90.99 554.72,80.72 564.99,72.83 576.96,67.88 589.8,66.19 602.64,67.88 614.61,72.83 624.88,80.72 632.77,90.99 637.72,102.96 639.41,115.8
  pour cut-out: 477.09,385.8 476.01,391.27 472.91,395.91 468.27,399.01 462.8,400.09 457.33,399.01 452.69,395.91 449.59,391.27 448.51,385.8 449.59,380.33 452.69,375.69 457.33,372.59 462.8,371.51 468.27,372.59 472.91,375.69 476.01,380.33 477.09,385.8
  pour cut-out: 533.66,215.8 532.16,227.15 527.78,237.73 520.81,246.81 511.73,253.78 501.15,258.16 489.8,259.66 478.45,258.16 467.87,253.78 458.79,246.81 451.82,237.73 447.44,227.15 445.94,215.8 447.44,204.45 451.82,193.87 458.79,184.79 467.87,177.82 478.45,173.44 489.8,171.94 501.15,173.44 511.73,177.82 520.81,184.79 527.78,193.87 532.16,204.45 533.66,215.8
  pour cut-out: 341.39,885.8 340.31,891.27 337.21,895.91 332.57,899.01 327.1,900.09 321.63,899.01 316.99,895.91 313.89,891.27 312.81,885.8 313.89,880.33 316.99,875.69 321.63,872.59 327.1,871.51 332.57,872.59 337.21,875.69 340.31,880.33 341.39,885.8
  pour cut-out: 439.41,115.8 437.72,128.64 432.77,140.61 424.88,150.88 414.61,158.77 402.64,163.72 389.8,165.41 376.96,163.72 364.99,158.77 354.72,150.88 346.83,140.61 341.88,128.64 340.19,115.8 341.88,102.96 346.83,90.99 354.72,80.72 364.99,72.83 376.96,67.88 389.8,66.19 402.64,67.88 414.61,72.83 424.88,80.72 432.77,90.99 437.72,102.96 439.41,115.8
  pour cut-out: 266.13,865.8 264.89,872.05 261.35,877.35 256.05,880.89 249.8,882.13 243.55,880.89 238.25,877.35 234.71,872.05 233.47,865.8 234.71,859.55 238.25,854.25 243.55,850.71 249.8,849.47 256.05,850.71 261.35,854.25 264.89,859.55 266.13,865.8
  pour cut-out: 293.63,890.8 292.39,897.05 288.85,902.35 283.55,905.89 277.3,907.13 271.05,905.89 265.75,902.35 262.21,897.05 260.97,890.8 262.21,884.55 265.75,879.25 271.05,875.71 277.3,874.47 283.55,875.71 288.85,879.25 292.39,884.55 293.63,890.8
  pour cut-out: 275.8,575.8 274.72,581.27 271.62,585.91 266.98,589.01 261.51,590.09 256.04,589.01 251.4,585.91 248.3,581.27 247.22,575.8 248.3,570.33 251.4,565.69 256.04,562.59 261.51,561.51 266.98,562.59 271.62,565.69 274.72,570.33 275.8,575.8
  pour cut-out: 233.93,379.8 232.85,385.27 229.75,389.91 225.11,393.01 219.64,394.09 214.17,393.01 209.53,389.91 206.43,385.27 205.35,379.8 206.43,374.33 209.53,369.69 214.17,366.59 219.64,365.51 225.11,366.59 229.75,369.69 232.85,374.33 233.93,379.8
  pour cut-out: 214.25,574.8 213.17,580.27 210.07,584.91 205.43,588.01 199.96,589.09 194.49,588.01 189.85,584.91 186.75,580.27 185.67,574.8 186.75,569.33 189.85,564.69 194.49,561.59 199.96,560.51 205.43,561.59 210.07,564.69 213.17,569.33 214.25,574.8
  pour cut-out: 211.13,308.3 209.89,314.55 206.35,319.85 201.05,323.39 194.8,324.63 188.55,323.39 183.25,319.85 179.71,314.55 178.47,308.3 179.71,302.05 183.25,296.75 188.55,293.21 194.8,291.97 201.05,293.21 206.35,296.75 209.89,302.05 211.13,308.3
  pour cut-out: 168.63,308.3 167.39,314.55 163.85,319.85 158.55,323.39 152.3,324.63 146.05,323.39 140.75,319.85 137.21,314.55 135.97,308.3 137.21,302.05 140.75,296.75 146.05,293.21 152.3,291.97 158.55,293.21 163.85,296.75 167.39,302.05 168.63,308.3
  pour cut-out: 161.43,220.8 160.35,226.27 157.25,230.91 152.61,234.01 147.14,235.09 141.67,234.01 137.03,230.91 133.93,226.27 132.85,220.8 133.93,215.33 137.03,210.69 141.67,207.59 147.14,206.51 152.61,207.59 157.25,210.69 160.35,215.33 161.43,220.8
  pour cut-out: 127.09,427.9 126.01,433.37 122.91,438.01 118.27,441.11 112.8,442.19 107.33,441.11 102.69,438.01 99.59,433.37 98.51,427.9 99.59,422.43 102.69,417.79 107.33,414.69 112.8,413.61 118.27,414.69 122.91,417.79 126.01,422.43 127.09,427.9
  pour cut-out: 126.13,308.3 124.89,314.55 121.35,319.85 116.05,323.39 109.8,324.63 103.55,323.39 98.25,319.85 94.71,314.55 93.47,308.3 94.71,302.05 98.25,296.75 103.55,293.21 109.8,291.97 116.05,293.21 121.35,296.75 124.89,302.05 126.13,308.3
  pour cut-out: 83.63,308.3 82.39,314.55 78.85,319.85 73.55,323.39 67.3,324.63 61.05,323.39 55.75,319.85 52.21,314.55 50.97,308.3 52.21,302.05 55.75,296.75 61.05,293.21 67.3,291.97 73.55,293.21 78.85,296.75 82.39,302.05 83.63,308.3
  pour cut-out: 109.26,209.8 107.4,219.16 102.1,227.1 94.16,232.4 84.8,234.26 75.44,232.4 67.5,227.1 62.2,219.16 60.34,209.8 62.2,200.44 67.5,192.5 75.44,187.2 84.8,185.34 94.16,187.2 102.1,192.5 107.4,200.44 109.26,209.8
  pour cut-out: 327.09,680.8 326.01,686.27 322.91,690.91 318.27,694.01 312.8,695.09 307.33,694.01 302.69,690.91 299.59,686.27 298.51,680.8 299.59,675.33 302.69,670.69 307.33,667.59 312.8,666.51 318.27,667.59 322.91,670.69 326.01,675.33 327.09,680.8
  pour cut-out: 934.09,658.3 933.01,663.77 929.91,668.41 925.27,671.51 919.8,672.59 914.33,671.51 909.69,668.41 906.59,663.77 905.51,658.3 906.59,652.83 909.69,648.19 914.33,645.09 919.8,644.01 925.27,645.09 929.91,648.19 933.01,652.83 934.09,658.3
  pour cut-out: 239.09,253.3 238.01,258.77 234.91,263.41 230.27,266.51 224.8,267.59 219.33,266.51 214.69,263.41 211.59,258.77 210.51,253.3 211.59,247.83 214.69,243.19 219.33,240.09 224.8,239.01 230.27,240.09 234.91,243.19 238.01,247.83 239.09,253.3
  pour cut-out: 201.59,220.3 200.51,225.77 197.41,230.41 192.77,233.51 187.3,234.59 181.83,233.51 177.19,230.41 174.09,225.77 173.01,220.3 174.09,214.83 177.19,210.19 181.83,207.09 187.3,206.01 192.77,207.09 197.41,210.19 200.51,214.83 201.59,220.3
  pour cut-out: 338.63,263.3 337.39,269.55 333.85,274.85 328.55,278.39 322.3,279.63 316.05,278.39 310.75,274.85 307.21,269.55 305.97,263.3 307.21,257.05 310.75,251.75 316.05,248.21 322.3,246.97 328.55,248.21 333.85,251.75 337.39,257.05 338.63,263.3
  pour cut-out: 439.41,315.8 437.72,328.64 432.77,340.61 424.88,350.88 414.61,358.77 402.64,363.72 389.8,365.41 376.96,363.72 364.99,358.77 354.72,350.88 346.83,340.61 341.88,328.64 340.19,315.8 341.88,302.96 346.83,290.99 354.72,280.72 364.99,272.83 376.96,267.88 389.8,266.19 402.64,267.88 414.61,272.83 424.88,280.72 432.77,290.99 437.72,302.96 439.41,315.8
  text ".Layer_Name" at 577,-858.49 h60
